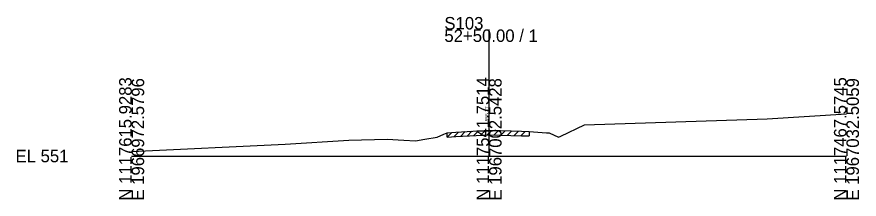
# Model space of a CAD drawing. Extents: x -26 to 163, y -10 to 24018.
# Drawn here: x -25.7 to 162.8, y 1990.3 to 2031.3 of the extents above; entities that cross this region are included whole.
import ezdxf

# ---------------------------------------------------------------- set-up
doc = ezdxf.new("R2010")
doc.units = 0
for name, color, linetype in [('RD_GPK_XS_Cell', 7, 'Continuous'), ('RD_XS_ExGround', 7, 'Continuous'), ('RD_XS_ExPaveRet', 7, 'Continuous'), ('RD_XS_TX_Elev_EX', 7, 'Continuous')]:
    doc.layers.add(name, color=color, linetype=linetype)

msp = doc.modelspace()

# ---------------------------------------------------------------- linework, layer by layer
at = {"layer": 'RD_GPK_XS_Cell'}
for p, q in [((80, 2000), (80, 2028.41)), ((0, 2000), (80, 2000)), ((80, 2000), (160, 2000))]:
    msp.add_line(p, q, dxfattribs=at)
at = {"layer": 'RD_XS_ExGround'}
msp.add_lwpolyline([(0, 2000.99), (34.4, 2002.68), (48.65, 2003.56), (57.2, 2003.81), (60.95, 2003.56), (63.56, 2003.42), (65.65, 2003.78), (68.41, 2004.26), (69.9, 2004.94), (70.61, 2005.22), (72.59, 2005.35), (80.2, 2005.78), (87.29, 2005.55), (89, 2005.5), (92.87, 2005.22), (93.48, 2005.18), (95.58, 2004.21), (96.05, 2004.49), (101.33, 2006.97), (142.22, 2008.36), (160, 2009.47)], dxfattribs=at)
at = {"layer": 'RD_XS_ExPaveRet'}
for p, q in [((70.61, 2004.22), (71.68, 2005.29)), ((70.61, 2004.22), (70.61, 2005.22)), ((70.61, 2004.22), (72.59, 2004.35)), ((72.11, 2004.32), (73.18, 2005.38)), ((72.59, 2004.35), (80.2, 2004.78)), ((73.61, 2004.41), (74.67, 2005.47)), ((75.11, 2004.49), (76.17, 2005.55)), ((76.61, 2004.58), (77.67, 2005.64)), ((78.11, 2004.66), (79.17, 2005.72)), ((79.61, 2004.74), (80.63, 2005.76)), ((80.2, 2004.78), (87.29, 2004.55)), ((81.11, 2004.75), (82.08, 2005.72)), ((82.61, 2004.7), (83.58, 2005.67)), ((84.11, 2004.65), (85.08, 2005.62)), ((85.61, 2004.6), (86.58, 2005.57)), ((87.11, 2004.55), (88.08, 2005.52)), ((87.29, 2004.55), (89, 2004.5)), ((89, 2005.5), (89, 2004.5))]:
    msp.add_line(p, q, dxfattribs=at)

# ---------------------------------------------------------------- texts
at = {"layer": 'RD_GPK_XS_Cell'}
for s, p in [('S103', (70, 2028.41)), ('52+50.00 / 1', (70, 2025.61)), ('EL 551', (-26, 1998.6))]:
    msp.add_text(s, height=2.8, dxfattribs=at).set_placement(p)
for s, p in [('N 1117615.9283', (0, 1990)), ('E 1966972.5796', (2.8, 1990)), ('N 1117541.7514', (80, 1990)), ('E 1967002.5428', (82.8, 1990)), ('N 1117467.5745', (160, 1990)), ('E 1967032.5059', (162.8, 1990))]:
    msp.add_text(s, height=2.8, rotation=90, dxfattribs=at).set_placement(p)
at = {"layer": 'RD_XS_TX_Elev_EX'}
msp.add_text('556.77', height=0.8, rotation=90, dxfattribs=at).set_placement((79.9, 2007.77))

doc.saveas('drawing.dxf')
